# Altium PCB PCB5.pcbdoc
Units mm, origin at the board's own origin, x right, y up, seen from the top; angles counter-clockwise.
Board outline 9.4 x 9.02 mm, 2 copper layers (Top Layer, Bottom Layer); 3 components, 4 nets, 7 pads, 2 vias.
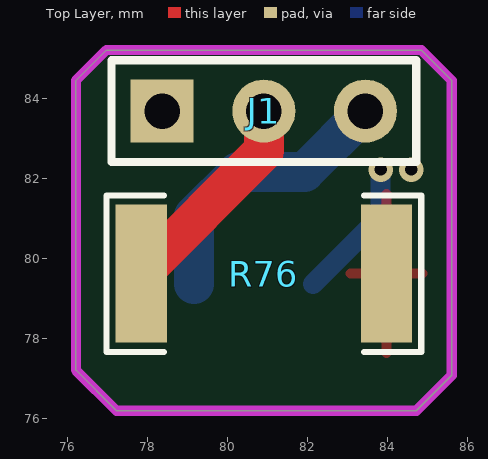
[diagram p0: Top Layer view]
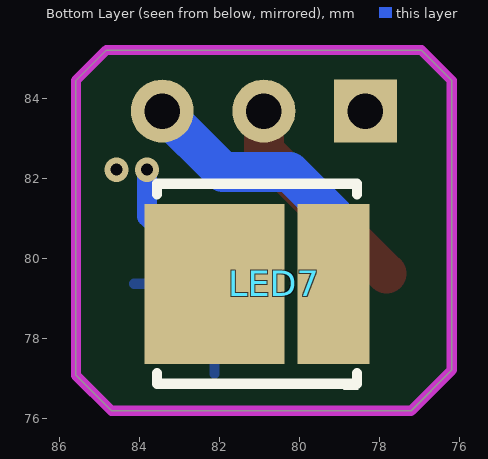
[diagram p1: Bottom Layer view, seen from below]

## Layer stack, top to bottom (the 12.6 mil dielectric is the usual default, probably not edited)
Top Layer: signal copper (thickness not stored)
Dielectric: dielectric 0.32, FR-4, Dk 4.8
Bottom Layer: signal copper (thickness not stored)

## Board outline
85.598,84.328 85.598,84.455 84.836,85.217 76.962,85.217 76.2,84.455 76.2,77.216 77.216,76.2 84.709,76.2 85.598,77.089

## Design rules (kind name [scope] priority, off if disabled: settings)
BoardOutlineClearance copperThickness1oz [All] p0: genericclearance=0.254 ignorepadtopadclearanceinfootprint=FALSE except(0: Arc-SplitContinuation Track-SplitContinuation SMDPad-SplitContinuation THPad-SplitContinuation Via-SplitContinuation Fill-SplitContinuation Poly-SplitContinuation Region-SplitContinuation Text-SplitContinuation; 0.152: Track-CutoutEdge SMDPad-CutoutEdge THPad-CutoutEdge Via-CutoutEdge Region-CutoutEdge; 0.3: Track-OutlineEdge SMDPad-OutlineEdge THPad-OutlineEdge Via-OutlineEdge Fill-OutlineEdge Region-OutlineEdge Poly-OutlineEdge Text-OutlineEdge Fill-CutoutEdge)
BoardOutlineClearance copperThickness2oz [All] p0: genericclearance=0.254 ignorepadtopadclearanceinfootprint=FALSE except(0: Arc-SplitContinuation Track-SplitContinuation SMDPad-SplitContinuation THPad-SplitContinuation Via-SplitContinuation Fill-SplitContinuation Poly-SplitContinuation Region-SplitContinuation Text-SplitContinuation; 0.152: Track-CutoutEdge SMDPad-CutoutEdge THPad-CutoutEdge Via-CutoutEdge Region-CutoutEdge; 0.3: Track-OutlineEdge SMDPad-OutlineEdge THPad-OutlineEdge Via-OutlineEdge Fill-OutlineEdge Region-OutlineEdge Poly-OutlineEdge Text-OutlineEdge Fill-CutoutEdge)
Clearance copperThickness1oz [(InNet('3V3_VDD') OR InNet('LED7_2') OR InNet('$3N4479') OR InNet('IR_TX'))] p1: gap=0.178 ignorepadtopadclearanceinfootprint=FALSE except(0.102: Track-Track; 0.152: Track-SMDPad SMDPad-SMDPad Track-THPad SMDPad-THPad THPad-THPad Track-Via SMDPad-Via THPad-Via Via-Via SMDPad-Fill THPad-Fill Via-Fill Fill-Fill Track-Region SMDPad-Region THPad-Region Via-Region Region-Region Track-Poly SMDPad-Poly THPad-Poly Via-Poly Fill-Poly Region-Poly Poly-Poly Track-Text SMDPad-Text THPad-Text Via-Text Fill-Text Region-Text Poly-Text Text-Text; 0.175: Track-Hole SMDPad-Hole THPad-Hole Via-Hole Fill-Hole Region-Hole Poly-Hole Text-Hole Sheet-Hole; 0.3: Track-Fill Fill-Region Track-Sheet SMDPad-Sheet THPad-Sheet Via-Sheet Fill-Sheet Region-Sheet Poly-Sheet Text-Sheet)
Clearance copperThickness2oz [All] p1: gap=0.178 ignorepadtopadclearanceinfootprint=FALSE except(0.152: Track-SMDPad SMDPad-SMDPad Track-THPad SMDPad-THPad THPad-THPad Track-Via SMDPad-Via THPad-Via Via-Via SMDPad-Fill THPad-Fill Via-Fill Fill-Fill Track-Region SMDPad-Region THPad-Region Via-Region Region-Region Track-Poly SMDPad-Poly THPad-Poly Via-Poly Fill-Poly Region-Poly Poly-Poly Track-Text SMDPad-Text THPad-Text Via-Text Fill-Text Region-Text Poly-Text Text-Text; 0.175: Track-Hole SMDPad-Hole THPad-Hole Via-Hole Fill-Hole Region-Hole Poly-Hole Text-Hole Sheet-Hole; 0.203: Track-Track; 0.3: Track-Fill Fill-Region Track-Sheet SMDPad-Sheet THPad-Sheet Via-Sheet Fill-Sheet Region-Sheet Poly-Sheet Text-Sheet)
DiffPairsRouting differentialPair [All] p1: maxuncoupledlength=10 minlimit=6 maxlimit=6 mostfreqgap=6 toplayer_minwidth=5 toplayer_prefwidth=10 toplayer_maxwidth=100 bottomlayer_minwidth=5 bottomlayer_prefwidth=10 bottomlayer_maxwidth=100
PasteMaskExpansion pasteMaskExpansion [All] p1: expansion=0
PlaneConnect innerPlane [All] p1: planeconnectstyle=Relief reliefexpansion=0.508 reliefentries=4 reliefconductorwidth=0.254 reliefairgap=0.254
PolygonConnect copperRegion [All] p1: connectstyle=Relief reliefentries=4 reliefconductorwidth=10 polygonreliefangle="90 Angle" airgapwidth=10
RoutingVias viaSize [All] p1: viastyle="Through Hole" holewidth=12.0078 minholewidth=11.811 maxholewidth=248.0314 width=24.0158 minwidth=19.685 maxwidth=393.7008
SolderMaskExpansion solderMaskExpansion [All] p1: useseparateexpansions=TRUE expansion=2 expansionbottom=2
Width copperThickness1oz [All] p1: maxlimit=100 minlimit=5 preferedwidth=10
Width copperThickness2oz [All] p1: maxlimit=100 minlimit=8 preferedwidth=10

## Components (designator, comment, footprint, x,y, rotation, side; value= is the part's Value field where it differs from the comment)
J1 "HDR-M-2.54_1x3" HDR-M-2.54_1X3 80.899,83.693 r0 top
LED7 "JNJ-50JI0111W140/28MIL-D/845-860NM" LED-SMD_L5.0-W5.0-LS5.3_C9900102386 80.645,79.375 r180 bottom
R76 "2Ω" R2512 80.899,79.629 r180 top

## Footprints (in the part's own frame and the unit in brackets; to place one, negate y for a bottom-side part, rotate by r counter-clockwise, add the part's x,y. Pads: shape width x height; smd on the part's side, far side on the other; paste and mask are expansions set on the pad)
HDR-M-2.54_1X3 [mil]
  rect 62x62 hole 35: 1(-100.01,-0.01)
  round 62 hole 35: 2(-0.01,-0.01) 3(99.99,-0.01)
  silkscreen extent -150,-50 150,50
LED-SMD_L5.0-W5.0-LS5.3_C9900102386 [mm]
  rect 3.5x4 smd: 1(-1.487,0)
  rect 1.8x4 smd: 2(1.488,0)
  silkscreen extent -2.92,-2.65 2.1,2.5
R2512 [mm]
  rect 1.283x3.456 smd: 1(-3.066,0) 2(3.066,0)
  silkscreen extent -3.94,-1.96 3.94,1.96

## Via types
v1: diameter 0.61, hole 0.305, Top Layer to Bottom Layer, 2 vias

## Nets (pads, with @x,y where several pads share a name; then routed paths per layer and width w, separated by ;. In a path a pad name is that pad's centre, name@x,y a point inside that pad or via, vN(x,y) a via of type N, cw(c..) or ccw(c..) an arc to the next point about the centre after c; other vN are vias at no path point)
3V3_VDD: J1.2 R76.2 | length 5.3
  Top Layer w1: R76.2 80.899,82.695 J1.2
$3N4479: LED7.1 R76.1 | length 3.6
  Bottom Layer w0.5: LED7.1 83.82,81.063 v1(83.82,82.228)
  other v1: 84.582,82.228
IR_TX: J1.1
LED7_2: J1.3 LED7.2 | length 7.1
  Bottom Layer w1: LED7.2 79.157,81.072 80.254,82.169 81.915,82.169 J1.3

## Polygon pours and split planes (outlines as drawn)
$3N4479 on Bottom Layer (solid, remove dead copper, pour order 2): 85.598,76.305 85.598,82.695 80.224,82.695 80.01,82.482 80.01,77.153 80.962,76.2 85.493,76.2
$3N4479 on Top Layer (solid, remove dead copper, pour order 0): 81.915,82.736 85.285,82.736 85.598,82.423 85.598,77.089 84.709,76.2 81.915,78.994

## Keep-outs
Board Outline Layer:
  the board outline again, w0.254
